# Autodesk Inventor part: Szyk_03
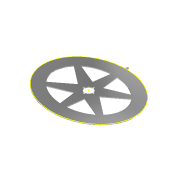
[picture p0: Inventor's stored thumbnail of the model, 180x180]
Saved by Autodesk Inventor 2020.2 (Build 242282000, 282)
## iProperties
Created: 2016-07
Part Number: Szyk_03
Material: Ogólny
Document SubType Name: Modeling
Designer: F.Stasiak
Density: 1 g/cm^3
Appearance: Chrom — polerowany
Manager: www.cadconsulting.pl
Company: Fabian Stasiak CAD Consulting
Author: F.Stasiak
Subject: Zbiór ćwiczeń. Autodesk Inventor 2020. Kurs podstawowy
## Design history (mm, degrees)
sketch "Szkic1" dims "d0" = 160, "d1" = 130
  geometry: 2 further points; 1 other entity
  constraints: 1 coincident, 2 other
extrude "Wyciągnięcie proste1" new body sketch "Szkic1" distance "d2" = 3; taper "d3" = 0 deg
sketch "Szkic4" dims "d14" = 40
  geometry: L1 (-2.5, 20)-(2.5, 20); L2 (2.5, 20)-(2.5, -20); L3 (2.5, -20)-(-2.5, -20); L4 (-2.5, -20)-(-2.5, 20); L5 (-2.5, 20)-(2.5, -20); L6 (2.5, 20)-(-2.5, -20); L7 (-20, 2.5)-(20, 2.5); L8 (20, 2.5)-(20, -2.5); L9 (20, -2.5)-(-20, -2.5); L10 (-20, -2.5)-(-20, 2.5); L11 (-20, 2.5)-(20, -2.5); L12 (20, 2.5)-(-20, -2.5); C1 r 15 at (0, 0); C2 r 35 at (0, 0); 1 further point; 1 other entity
  constraints: 24 end point, 4 midpoint, 4 parallel, 2 centre point, 2 coincident, 2 horizontal, 2 perpendicular, 1 other
  dimensions: "d15" = 30 diameter of C1; "d16" = 5 distance of L2.end L3.end; "d17" = 40 distance of L1.end L2.end; "d18" = 40 distance of L8.end L9.end (= d17); "d19" = 5 distance of L7.end L8.end (= d16); "d20" = 70 diameter of C2
extrude "Wyciągnięcie proste3" cut sketch "Szkic4" extent not by distance; stored distance "d21" = 3; taper "d22" = 0 deg
sketch "Szkic5"
  geometry: L1 (18.836, 29.499)-(6, 127); L2 (-18.836, 29.499)-(-6, 127); L3 (-6, 127)-(6, 127); A1 r 35 centre (0, 0) between (18.836, 29.499) and (-18.836, 29.499) reference; A2 r 15 centre (0, 0) between (14.79, 2.5) and (2.5, 14.79) reference; A3 r 35 centre (0, 0) between (18.836, 29.499) and (-18.836, 29.499) reference; 2 further points; 1 other entity
  constraints: 6 end point, 4 point on circle, 1 equal length, 1 horizontal, 1 midpoint, 1 vertical alignment, 1 other
  dimensions: "d23" = 15 deg angle of L1 L2; "d24" = 127 distance from line of L3 A1.centre; "d25" = 12 distance of L2.end L1.end
extrude "Wyciągnięcie proste4" join sketch "Szkic5" distance "d26" = 3; taper "d27" = 0 deg
pattern_circular "Szyk kołowy1" dims angle "d29" = 360 deg
sketch "Szkic2"
  geometry: L1 (-4.5, 129)-(-1.821, 139); L2 (-1.821, 139)-(1.821, 139); L3 (1.821, 139)-(4.5, 129); L4 (4.5, 129)-(-4.5, 129); 4 further points; 2 other entities
  constraints: 8 end point, 2 horizontal, 2 midpoint, 2 vertical alignment, 2 other
  dimensions: "d4" = 129 distance from line of L4 point (0, 0); "d5" = 10 distance between parallel lines of L2 L4; "d6" = 9 distance of L3.end L1.start; "d7" = 30 deg angle of L1 L3
extrude "Wyciągnięcie proste2" join sketch "Szkic2" distance "d8" = 3; taper "d9" = 0 deg
fillet "Zaokrąglenie1" dims "d10" = 3.5
sketch "KRAWĘDŹ ELIPSY"
  geometry: 1 further point; 1 other entity
  constraints: 1 other
node "Bryła1"
